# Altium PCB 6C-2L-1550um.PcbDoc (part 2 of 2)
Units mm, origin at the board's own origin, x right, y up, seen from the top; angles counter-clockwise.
Board outline 120.5 x 75.92 mm, 2 copper layers (Top Layer, Bottom Layer), stack 1.586 mm thick; 122 components, 111 nets, 420 pads, 133 vias.
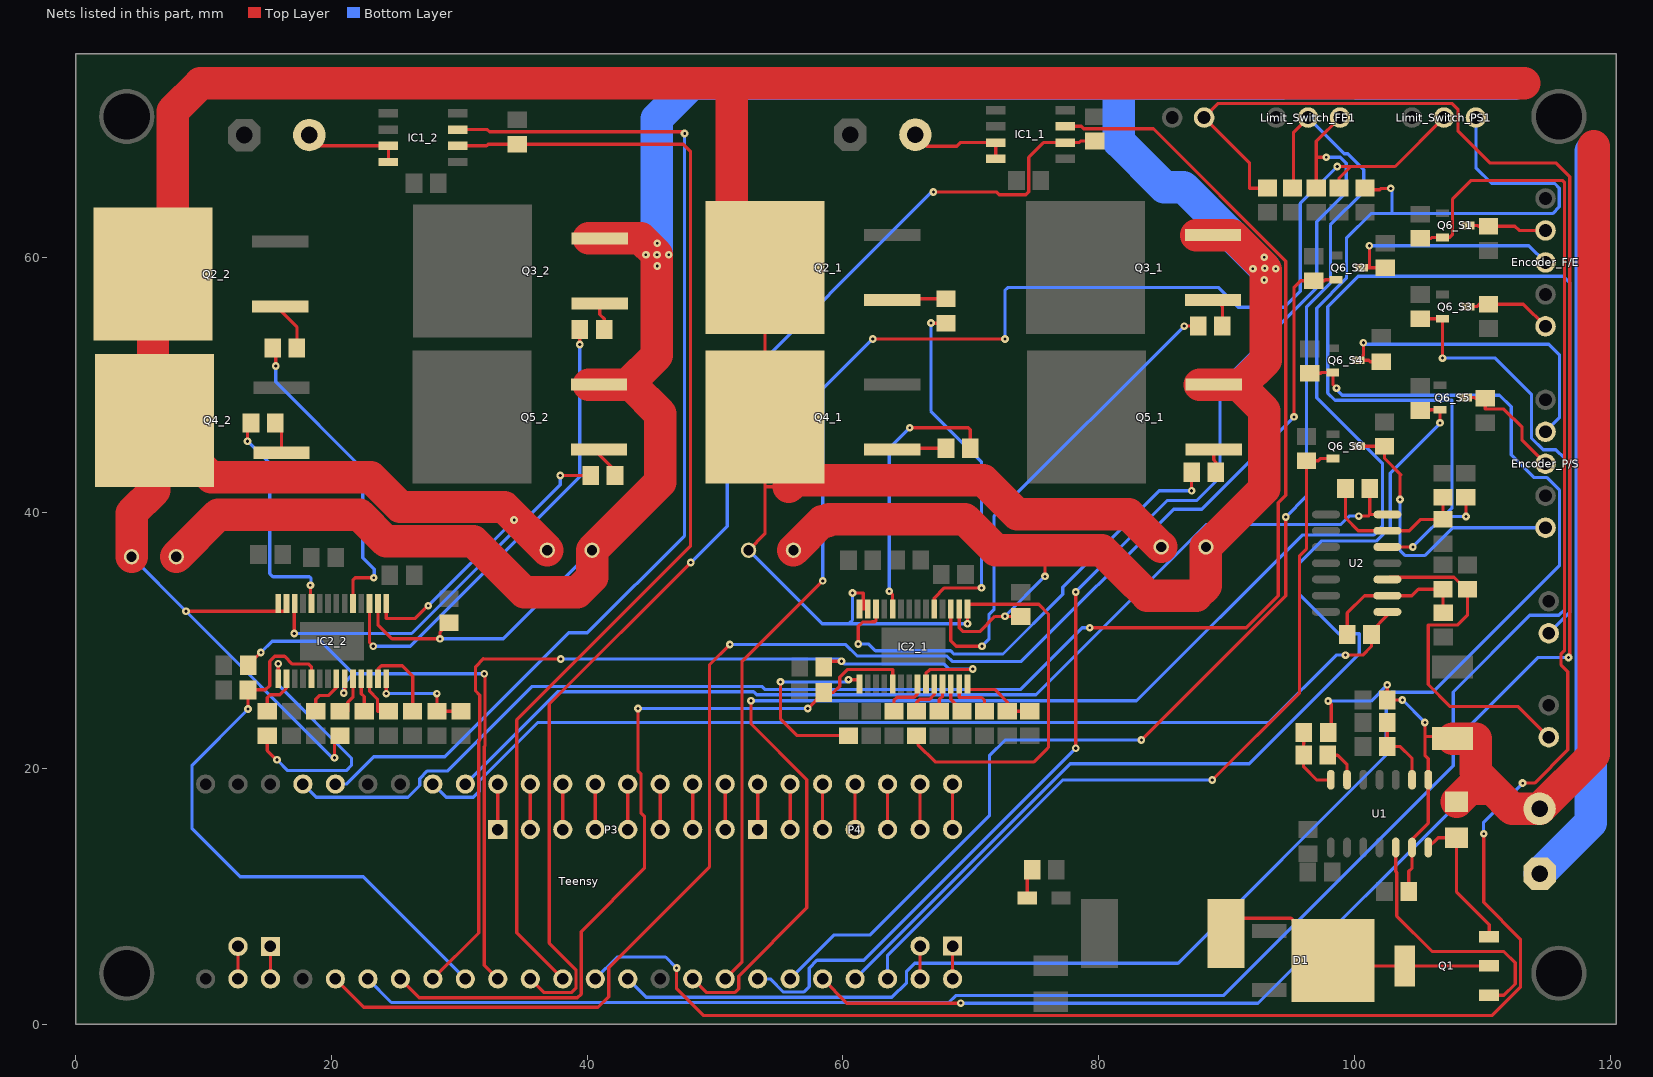
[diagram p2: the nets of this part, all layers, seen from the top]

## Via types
v1: diameter 0.6, hole 0.25, Top Layer to Bottom Layer, 89 vias
v2: diameter 0.6, hole 0.2, Top Layer to Bottom Layer, 44 vias

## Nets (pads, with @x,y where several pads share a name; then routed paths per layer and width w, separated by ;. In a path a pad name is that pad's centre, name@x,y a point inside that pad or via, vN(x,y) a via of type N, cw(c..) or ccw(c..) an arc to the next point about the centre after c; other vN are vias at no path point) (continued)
NetC14_1_2: C14_1.2 IC2_1.15 | length 15.4
  Top Layer w0.254: v1(55.13,26.784) 55.13,23.879 56.426,22.584 C14_1.2@60.452,22.584 ; v1(60.439,26.962) 61.298,26.962 IC2_1.15@61.298,26.611
  Bottom Layer w0.254: v1(55.13,26.784) 60.261,26.784 v1(60.439,26.962)
NetC14_2_1: C14_2.1 IC2_2.16 | length 3.6
  Top Layer w0.254: C14_2.1@14.986,24.486 14.986,25.539 15.228,25.781 15.977,25.781 16.491,26.295 IC2_2.16@16.491,27.034
NetC14_2_2: C14_2.2 IC2_2.15 | length 20.1
  Top Layer w0.254: C14_2.2@14.986,22.586 14.986,21.411 15.697,20.7 v1(15.748,20.7) ; IC2_2.15@15.841,27.034 v1(15.841,28.206)
  Bottom Layer w0.254: v1(15.748,20.7) 16.598,19.85 21.17,19.85 21.577,20.256 21.577,20.816 15.841,26.552 v1(15.841,28.206)
NetD1_3: D1.3 L1.1 Q1.2 Q1.4 | length 23.3
  Top Layer w0.254: L1.1@89.964,7.112 89.964,8.293 95.053,8.293 D1.3@98.346,5 98.774,4.572 Q1.4@103.934,4.572 Q1.2@110.534,4.572
NetD2_2: D2.2 R4.2 | length 2.4
  Top Layer w0.254: D2.2@74.419,9.881 74.419,11.706 R4.2@74.803,12.09
NetEncoder_F/E_2: Encoder_F/E.2 Q6_S1.3 R44_S1.1 | length 6.2
  Top Layer w0.254: Q6_S1.3@108.888,62.484 109.639,62.484 109.705,62.418 R44_S1.1@110.49,62.418 112.56,62.418 112.886,62.092 Encoder_F/E.2@114.956,62.092
NetEncoder_F/E_3: Encoder_F/E.3 Q6_S2.3 R44_S2.1 | length 17.9
  Top Layer w0.254: Q6_S2.3@100.568,59.182 101.18,59.182 ; v1(101.18,60.896) 101.18,59.182 ; R44_S2.1@102.424,59.182 101.18,59.182
  Bottom Layer w0.254: v1(101.18,60.896) 113.652,60.896 Encoder_F/E.3@114.956,59.592
NetEncoder_F/E_5: Encoder_F/E.5 Q6_S3.3 R44_S3.1 | length 6.9
  Top Layer w0.254: Q6_S3.3@108.888,56.134 109.588,56.134 109.776,56.322 R44_S3.1@110.49,56.322 113.226,56.322 Encoder_F/E.5@114.956,54.592
NetEncoder_P/S_2: Encoder_P/S.2 Q6_S4.3 R44_S4.1 | length 25.6
  Top Layer w0.254: v1(100.711,53.315) 100.711,52.335 Q6_S4.3@100.314,51.938 101.13,51.938 101.252,51.816 R44_S4.1@102.108,51.816
  Bottom Layer w0.254: v1(100.711,53.315) 100.826,53.2 115.201,53.2 116.039,52.362 116.039,47.427 Encoder_P/S.2@114.956,46.344
NetEncoder_P/S_3: Encoder_P/S.3 Q6_S5.3 R44_S5.1 | length 9.5
  Top Layer w0.254: Q6_S5.3@108.696,49.022 109.41,49.022 109.476,48.956 R44_S5.1@110.236,48.956 110.236,48.12 111.696,48.12 113.118,46.697 113.118,45.682 Encoder_P/S.3@114.956,43.844
NetEncoder_P/S_5: Encoder_P/S.5 Q6_S6.3 R44_S6.1 | length 23.2
  Top Layer w0.254: Q6_S6.3@100.33,45.212 R44_S6.1@102.362,45.212 102.362,44.259 103.632,42.989 103.581,42.938 v1(103.581,41.046)
  Bottom Layer w0.254: v1(103.581,41.046) 103.581,37.059 103.962,36.678 105.537,36.678 107.703,38.844 Encoder_P/S.5@114.956,38.844
NetIC1_1_3: IC1_1.3 IC1_1.4 P2_1.2 | length 8
  Top Layer w0.254: P2_1.2@65.675,69.579 66.572,68.682 68.909,68.682 69.189,68.961 IC1_1.3@71.964,68.961 IC1_1.4@71.964,67.691
NetIC1_1_6: IC1_1.6 R36_1.2 Teensy.11 | length 95.8
  Top Layer w0.254: Teensy.11@35.56,3.556 36.615,2.501 38.798,2.501 39.129,2.833 39.129,4.278 37.045,6.362 37.045,25.057 v1(48.108,36.119) ; v1(67.081,65.1) 72.009,65.1 72.225,64.884 74.307,64.884 74.536,65.112 74.536,67.805 75.692,68.961 IC1_1.6@77.388,68.961 78.473,68.961 78.6,69.088 R36_1.2@79.705,69.088
  Bottom Layer w0.254: v1(48.108,36.119) 50.952,38.964 50.952,49.098 66.954,65.1 v1(67.081,65.1)
NetIC1_1_7: IC1_1.7 Teensy.28 | length 131.8
  Top Layer w0.254: IC1_1.7@77.388,70.231 78.651,70.231 78.842,70.04 84.297,70.04 94.64,59.697 94.64,41.391 94.061,40.812 94.061,33.523 91.551,31.013 v2(79.299,31.013)
  Bottom Layer w0.254: Teensy.28@17.78,18.796 18.809,17.767 25.996,17.767 26.911,18.681 26.911,19.222 27.514,19.825 29.096,19.825 35.701,26.43 53.673,26.43 53.917,26.186 73.888,26.186 78.715,31.013 v2(79.299,31.013)
NetIC1_2_3: IC1_2.3 IC1_2.4 P2_2.2 | length 8.3
  Top Layer w0.254: P2_2.2@18.279,69.554 18.279,68.707 IC1_2.3@24.466,68.707 IC1_2.4@24.466,67.437
NetIC1_2_6: IC1_2.6 R36_2.2 Teensy.12 | length 90.3
  Top Layer w0.254: IC1_2.6@29.89,68.707 32.143,68.707 32.27,68.834 R36_2.2@34.544,68.834 47.523,68.834 48.082,68.275 48.082,37.389 34.505,23.812 34.505,7.151 Teensy.12@38.1,3.556
NetIC1_2_7: IC1_2.7 Teensy.29 | length 84.7
  Top Layer w0.254: IC1_2.7@29.89,69.977 32.206,69.977 32.379,69.805 47.493,69.805 v2(47.625,69.672)
  Bottom Layer w0.254: Teensy.29@20.32,18.796 21.177,18.796 23.308,20.927 28.877,20.927 38.569,30.619 40.017,30.619 47.625,38.227 v2(47.625,69.672)
NetIC2_1_3: IC2_1.3 R23_1.2 | length 37.8
  Top Layer w0.254: IC2_1.3@68.448,32.487 68.448,30.01 68.88,29.578 v1(70.878,29.578) ; v1(86.702,54.61) R23_1.2@87.784,54.61
  Bottom Layer w0.254: v1(70.878,29.578) 71.425,30.124 71.425,32.052 71.826,32.454 71.826,34.546 71.818,34.554 71.818,39.726 v1(86.702,54.61)
NetIC2_1_5: IC2_1.5 R22_1.2 | length 28.4
  Top Layer w0.254: v1(66.89,54.851) 66.899,54.842 R22_1.2@68.072,54.842 ; IC2_1.5@67.148,32.487 67.148,33.341 67.945,34.138 v1(70.841,34.138)
  Bottom Layer w0.254: v1(66.89,54.851) 66.89,47.967 70.841,44.017 v1(70.841,34.138)
NetIC2_1_10: IC2_1.10 R31_1.2 | length 21.2
  Top Layer w0.254: v2(63.627,33.884) 63.881,33.63 63.881,32.504 IC2_1.10@63.898,32.487 ; v2(65.227,46.66) 69.825,46.66 69.972,46.512 R31_1.2@69.972,45.058
  Bottom Layer w0.254: v2(63.627,33.884) 63.627,45.06 v2(65.227,46.66)
NetIC2_1_12: IC2_1.12 R33_1.2 | length 37.3
  Top Layer w0.254: v1(61.214,29.743) 61.214,31.14 61.543,31.47 62.289,31.47 62.302,31.483 62.488,31.483 62.598,31.593 IC2_1.12@62.598,32.487 ; v1(87.276,41.727) R33_1.2@87.276,43.18
  Bottom Layer w0.254: v1(61.214,29.743) 62.026,29.743 62.552,29.217 68.428,29.217 68.677,28.968 72.529,28.968 77.191,33.63 77.191,34.188 84.73,41.727 v1(87.276,41.727)
NetIC2_1_19: IC2_1.19 R34_1.1 Teensy.7 | length 62.2
  Top Layer w0.254: Teensy.7@25.4,3.556 26.87,2.086 39.248,2.086 39.536,2.374 39.536,7.252 44.488,12.204 44.488,16.269 44.209,16.548 44.209,19.594 43.98,19.824 v1(43.98,24.701) ; v1(57.251,24.701) 58.508,25.959 R34_1.1@58.517,25.959 59.27,25.959 59.753,26.441 59.753,27.165 60.337,27.749 63.898,27.749 IC2_1.19@63.898,26.611
  Bottom Layer w0.254: v1(43.98,24.701) v1(57.251,24.701)
NetIC2_1_22: IC2_1.22 R32_1.1 | length 3.7
  Top Layer w0.254: R32_1.1@63.995,24.484 63.995,25.336 64.253,25.594 65.57,25.594 65.848,25.872 IC2_1.22@65.848,26.611
NetIC2_1_23: IC2_1.23 R28_1.2 Teensy.8 | length 71.8
  Top Layer w0.254: Teensy.8@27.94,3.556 31.534,7.15 31.534,22.161 31.61,22.237 31.61,25.742 31.28,26.073 31.28,27.978 31.889,28.587 31.901,28.575 v1(37.948,28.575) ; R28_1.2@58.52,27.94 58.977,28.397 v1(59.893,28.397) ; IC2_1.23@66.498,26.611 66.498,27.459 66.789,27.749 70.116,27.749 v1(70.167,27.8)
  Bottom Layer w0.254: v1(37.948,28.575) 59.715,28.575 v1(59.893,28.397) 60.096,28.194 67.876,28.194 68.27,27.8 v1(70.167,27.8)
NetIC2_1_24: IC2_1.24 R30_1.1 | length 3.2
  Top Layer w0.254: R30_1.1@65.767,24.484 65.767,25.187 66.017,25.438 66.789,25.438 67.148,25.797 IC2_1.24@67.148,26.611
NetIC2_1_25: IC2_1.25 R29_1.1 | length 2.2
  Top Layer w0.254: R29_1.1@67.539,24.484 67.539,25.412 67.798,25.672 IC2_1.25@67.798,26.611
NetIC2_1_26: IC2_1.26 R27_1.1 | length 2.8
  Top Layer w0.254: IC2_1.26@68.448,26.611 68.448,25.412 68.753,25.107 68.753,24.484 R27_1.1@69.31,24.484
NetIC2_1_27: IC2_1.27 R26_1.1 | length 4
  Top Layer w0.254: IC2_1.27@69.098,26.611 69.098,25.565 70.853,25.565 71.082,25.336 R26_1.1@71.082,24.484
NetIC2_1_28: IC2_1.28 R24_1.2 R25_1.1 | length 6.4
  Top Layer w0.254: IC2_1.28@69.748,26.611 69.748,26.2 71.869,26.2 72.854,25.215 R25_1.1@72.854,24.484 R24_1.2@74.625,24.484
NetIC2_2_3: IC2_2.3 R23_2.2 | length 36.6
  Top Layer w0.254: IC2_2.3@22.991,32.91 22.991,29.857 v1(23.27,29.578) ; v1(39.433,53.174) 39.436,53.177 R23_2.2@39.436,54.356
  Bottom Layer w0.254: v1(23.27,29.578) 26.174,29.578 39.433,42.837 v1(39.433,53.174)
NetIC2_2_5: IC2_2.5 R22_2.2 | length 25
  Top Layer w0.254: R22_2.2@15.408,52.908 15.248,52.748 15.646,52.349 v1(15.646,51.486) ; IC2_2.5@21.691,32.91 21.691,34.747 21.869,34.925 v2(23.317,34.925)
  Bottom Layer w0.254: v1(15.646,51.486) 15.646,50.241 22.454,43.434 22.454,36.5 23.355,35.598 23.355,34.963 v2(23.317,34.925) v2@23.241,34.925
NetIC2_2_10: IC2_2.10 R31_2.2 | length 18.1
  Top Layer w0.254: v1(13.449,45.605) 13.449,46.769 R31_2.2@13.721,47.041 ; v2(18.364,34.341) 18.364,32.987 IC2_2.10@18.441,32.91
  Bottom Layer w0.254: v1(13.449,45.605) 15.176,43.878 15.176,35.255 15.43,35.001 18.288,35.001 18.415,34.874 18.415,34.29 v2(18.364,34.341)
NetIC2_2_12: IC2_2.12 R33_2.2 | length 31.1
  Top Layer w0.254: v1@17.141,30.603 v1(17.106,30.568) 17.106,32.875 IC2_2.12@17.141,32.91 ; v1(37.897,42.926) R33_2.2@40.286,42.926
  Bottom Layer w0.254: v1(17.106,30.568) 26.276,30.568 37.897,42.189 v1(37.897,42.926)
NetIC2_2_19: IC2_2.19 R34_2.1 Teensy.9 | length 47.3
  Top Layer w0.254: v1(13.484,24.66) R34_2.1@13.484,26.162 14.846,26.162 15.176,26.492 15.176,28.384 15.582,28.79 16.344,28.79 16.954,28.181 18.238,28.181 18.441,27.978 IC2_2.19@18.441,27.034
  Bottom Layer w0.254: v1(13.484,24.66) 9.105,20.281 9.105,15.303 12.865,11.544 22.492,11.544 Teensy.9@30.48,3.556
NetIC2_2_22: IC2_2.22 R32_2.1 | length 3.6
  Top Layer w0.254: R32_2.1@18.777,24.486 18.777,25.42 19.087,25.73 19.795,25.73 20.391,26.326 IC2_2.22@20.391,27.034
NetIC2_2_23: IC2_2.23 R28_2.2 Teensy.10 | length 47.6
  Top Layer w0.254: R28_2.2@13.487,28.092 13.5,28.092 v1(14.49,29.083) ; v1(20.967,25.92) 21.041,25.994 IC2_2.23@21.041,27.034 ; v1(31.965,27.419) 32.016,27.368 32.016,21.773 31.965,21.722 31.965,4.611 Teensy.10@33.02,3.556
  Bottom Layer w0.254: v1(14.49,29.083) 15.379,29.972 19.176,29.972 21.729,27.419 ; v1@20.98,25.933 v1(20.967,25.92) 20.967,26.657 21.729,27.419 ; v1(31.965,27.419) 21.729,27.419
NetIC2_2_24: IC2_2.24 R30_2.1 | length 3.3
  Top Layer w0.254: R30_2.1@20.672,24.486 21.282,24.486 21.282,25.184 21.691,25.593 IC2_2.24@21.691,27.034
NetIC2_2_25: IC2_2.25 R29_2.1 | length 2.6
  Top Layer w0.254: IC2_2.25@22.341,27.034 22.341,25.868 22.568,25.641 R29_2.1@22.568,24.486
NetIC2_2_26: IC2_2.26 R27_2.1 | length 3.7
  Top Layer w0.254: IC2_2.26@22.991,27.034 22.991,26.055 23.609,25.438 23.609,24.486 R27_2.1@24.463,24.486
NetIC2_2_27: IC2_2.27 R26_2.1 | length 6.7
  Top Layer w0.254: IC2_2.27@23.641,27.034 23.641,27.781 23.914,28.054 25.539,28.054 26.359,27.234 R26_2.1@26.359,24.486
NetIC2_2_28: IC2_2.28 R24_2.2 R25_2.1 | length 8.4
  Top Layer w0.254: v1(24.291,25.869) IC2_2.28@24.291,27.034 ; v1(28.254,25.869) R25_2.1@28.254,24.486 R24_2.2@30.15,24.486
  Bottom Layer w0.254: v1(24.291,25.869) v1(28.254,25.869)
NetLimit_Switch_FE1_2: Limit_Switch_FE1.2 R6.2 Teensy.19 | length 101.9
  Top Layer w0.254: v1(83.35,22.237) 94.64,33.528 v1(94.64,39.675) ; R6.2@95.25,65.278 95.25,69.783 Limit_Switch_FE1.2@96.384,70.917
  Bottom Layer w0.254: Teensy.19@55.88,3.556 59.321,6.997 62.141,6.997 71.462,16.319 71.462,21.018 72.682,22.237 v1(83.35,22.237) ; v1(94.64,39.675) 96.253,41.287 96.253,56.095 98.132,57.975 98.132,62.522 100.736,65.126 100.736,66.847 99.504,68.079 99.221,68.079 Limit_Switch_FE1.2@96.384,70.917
NetLimit_Switch_FE1_3: Limit_Switch_FE1.3 R10.2 Teensy.18 | length 98.9
  Top Layer w0.254: v1(78.219,21.602) v1(78.219,33.82) ; R10.2@97.028,65.278 R10.2@97.028,65.415 97.028,69.061 Limit_Switch_FE1.3@98.884,70.917 ; 97.028,67.843 97.053,67.818 v2(97.815,67.818)
  Bottom Layer w0.254: Teensy.18@53.34,3.556 54.33,3.556 55.359,2.527 56.933,2.527 57.365,2.959 57.365,4.406 57.975,5.016 61.633,5.016 v1(78.219,21.602) ; v1(78.219,33.82) 85.369,40.97 87.681,40.97 89.496,42.786 89.496,50.05 97.066,57.619 97.066,62.776 99.377,65.087 99.377,67.349 98.908,67.818 v2(97.815,67.818)
NetLimit_Switch_PS1_2: Limit_Switch_PS1.2 R2.2 Teensy.17 | length 116.5
  Top Layer w0.254: Teensy.17@50.8,3.556 52.108,4.864 52.108,28.359 v1(58.432,34.683) ; v1(62.344,53.606) v1(72.682,53.606) ; v1(98.666,67.094) 99.72,67.094 ; R2.2@98.806,65.212 R2.2@98.806,65.415 98.806,66.179 99.72,67.094 ; Limit_Switch_PS1.2@107.012,70.917 103.188,67.094 99.72,67.094
  Bottom Layer w0.254: v1(58.432,34.683) 58.432,49.695 v1(62.344,53.606) ; v1(72.682,53.606) 72.682,57.416 72.885,57.619 89.396,57.619 90.932,56.083 94.539,56.083 95.777,57.322 95.777,64.205 v1(98.666,67.094)
NetLimit_Switch_PS1_3: Limit_Switch_PS1.3 R3.2 Teensy.16 | length 145.6
  Top Layer w0.254: Teensy.16@48.26,3.556 49.315,2.501 51.574,2.501 51.854,2.781 51.854,3.771 57.188,9.105 57.188,19.138 52.819,23.507 v1(52.819,25.311) ; R3.2@100.838,65.278 102.006,65.278 102.108,65.38 v1(102.845,65.38)
  Bottom Layer w0.254: v1(52.819,25.311) 82.969,25.311 95.923,38.265 101.511,38.265 102.196,38.95 102.196,43.878 97.066,49.009 97.066,56.019 99.384,58.338 99.384,61.487 101.307,63.411 115.506,63.411 116.035,63.94 116.035,65.396 115.658,65.773 110.731,65.773 109.512,66.992 Limit_Switch_PS1.3@109.512,70.917 ; v1(102.845,65.38) 102.958,65.266 102.958,63.411
NetP3_1: P3.1 Teensy.34 | length 3.7
  Top Layer w0.254: Teensy.34@33.02,18.796 33.02,15.494 P3.1@33.274,15.24
NetP3_2: P3.2 Teensy.35 | length 3.7
  Top Layer w0.254: Teensy.35@35.56,18.796 35.56,15.494 P3.2@35.814,15.24
NetP3_3: P3.3 Teensy.36 | length 3.7
  Top Layer w0.254: Teensy.36@38.1,18.796 38.1,15.494 P3.3@38.354,15.24
NetP3_4: P3.4 Teensy.37 | length 3.7
  Top Layer w0.254: Teensy.37@40.64,18.796 40.64,15.494 P3.4@40.894,15.24
NetP3_5: P3.5 Teensy.38 | length 3.7
  Top Layer w0.254: Teensy.38@43.18,18.796 43.18,15.494 P3.5@43.434,15.24
NetP3_6: P3.6 Teensy.39 | length 3.7
  Top Layer w0.254: Teensy.39@45.72,18.796 45.72,15.494 P3.6@45.974,15.24
NetP3_7: P3.7 Teensy.40 | length 3.7
  Top Layer w0.254: Teensy.40@48.26,18.796 48.26,15.494 P3.7@48.514,15.24
NetP3_8: P3.8 Teensy.41 | length 3.7
  Top Layer w0.254: Teensy.41@50.8,18.796 50.8,15.494 P3.8@51.054,15.24
NetP4_1: P4.1 Teensy.42 | length 3.7
  Top Layer w0.254: Teensy.42@53.34,18.796 53.34,15.494 P4.1@53.594,15.24
NetP4_2: P4.2 Teensy.43 | length 3.7
  Top Layer w0.254: Teensy.43@55.88,18.796 55.88,15.494 P4.2@56.134,15.24
NetP4_3: P4.3 Teensy.44 | length 3.7
  Top Layer w0.254: Teensy.44@58.42,18.796 58.42,15.494 P4.3@58.674,15.24
NetP4_4: P4.4 Teensy.45 | length 3.7
  Top Layer w0.254: Teensy.45@60.96,18.796 60.96,15.494 P4.4@61.214,15.24
NetP4_5: P4.5 Teensy.46 | length 3.7
  Top Layer w0.254: Teensy.46@63.5,18.796 63.5,15.494 P4.5@63.754,15.24
NetP4_6: P4.6 Teensy.47 | length 3.7
  Top Layer w0.254: Teensy.47@66.04,18.796 66.04,15.494 P4.6@66.294,15.24
NetP4_7: P4.7 Teensy.48 | length 3.7
  Top Layer w0.254: Teensy.48@68.58,18.796 68.58,15.494 P4.7@68.834,15.24
NetP5_1: P5.1 Teensy.3 | length 2.5
  Top Layer w0.254: Teensy.3@15.24,3.556 P5.1@15.24,6.096
NetP5_2: P5.2 Teensy.2 | length 2.5
  Top Layer w0.254: Teensy.2@12.7,3.556 P5.2@12.7,6.096
NetP6_1: P6.1 Teensy.24 | length 2.5
  Top Layer w0.254: Teensy.24@68.58,3.556 68.58,5.837 68.585,5.842 P6.1@68.834,5.842
NetP6_2: P6.2 Teensy.23 | length 2.4
  Top Layer w0.254: Teensy.23@66.04,3.556 66.04,5.588 P6.2@66.294,5.842
NetPt1_2: Pt1.2 R15.1 U2.3 | length 28
  Top Layer w0.254: U2.3@102.59,34.798 102.757,34.965 107.8,34.965 108.739,34.026 R15.1@108.864,34.026 ; R15.1@108.859,34.102 108.859,32.042 108.046,31.229 105.778,31.229 105.778,26.581 107.505,24.853 112.817,24.853 Pt1.2@115.21,22.46
NetPt2_2: Pt2.2 R19.1 U2.5 | length 83.8
  Top Layer w0.254: U2.5@102.59,37.338 v1(104.584,37.338) ; R19.1@108.712,41.148 108.737,41.123 v1(108.737,39.726)
  Bottom Layer w0.254: v1(104.584,37.338) 107.645,40.399 ; v1(108.737,39.726) 106.972,39.726 107.645,40.399 ; Pt2.2@115.21,30.588 116.852,32.23 116.852,58 116.344,58.508 100.317,58.508 97.929,56.121 97.929,49.369 98.492,48.806 107.645,48.806 107.645,40.399
NetQ1_1: Q1.1 U1.12 | length 20.3
  Top Layer w0.254: U1.12@103.246,13.836 103.246,11.95 103.314,11.882 103.314,8.47 106.083,5.702 111.696,5.702 112.585,4.813 112.585,3.161 111.696,2.272 Q1.1@110.534,2.272
NetQ1_3: Q1.3 R1.2 U1.14 | length 11.3
  Top Layer w0.254: U1.14@105.786,13.836 106.55,14.6 R1.2@108,14.6 108,10.35 110.553,7.797 110.553,6.872 Q1.3@110.534,6.872
NetQ2_1_1: Q2_1.1 R22_1.1 | length 4.3
  Top Layer w0.254: Q2_1.1@63.858,56.642 65.9,56.642 66,56.742 R22_1.1@68.072,56.742
NetQ2_2_1: Q2_2.1 R22_2.1 | length 3.8
  Top Layer w0.254: Q2_2.1@16.002,56.134 16.002,55.855 17.308,54.549 R22_2.1@17.308,52.908
NetQ3_1_1: Q3_1.1 R23_1.1 | length 2.5
  Top Layer w0.254: Q3_1.1@88.944,56.642 89.205,56.642 89.684,56.163 R23_1.1@89.684,54.61
NetQ3_2_1: Q3_2.1 R23_2.1 | length 2.2
  Top Layer w0.254: Q3_2.1@40.998,56.388 40.998,55.519 41.336,55.181 R23_2.1@41.336,54.356
NetQ4_1_1: Q4_1.1 R31_1.1 | length 4.3
  Top Layer w0.254: Q4_1.1@63.858,44.958 65.9,44.958 66,45.058 R31_1.1@68.072,45.058
NetQ4_2_1: Q4_2.1 R31_2.1 | length 2.5
  Top Layer w0.254: R31_2.1@15.621,47.041 16.106,46.556 Q4_2.1@16.106,44.704
NetQ5_1_1: Q5_1.1 R33_1.1 | length 1.8
  Top Layer w0.254: Q5_1.1@89.004,44.958 89.004,44.152 89.176,43.98 R33_1.1@89.176,43.18
NetQ5_2_1: Q5_2.1 R33_2.1 | length 2.5
  Top Layer w0.254: Q5_2.1@40.938,44.958 40.938,44.542 42.186,43.294 R33_2.1@42.186,42.926
NetQ6_S1_2: Q6_S1.2 R43_S1.1 Teensy.13 | length 159.4
  Top Layer w0.254: v1(47.002,4.406) 47.002,2.781 49.085,0.698 110.782,0.698 112.991,2.908 112.991,6.667 110.121,9.537 v2(110.121,14.897) ; R43_S1.1@105.156,61.468 105.981,61.468 106.047,61.534 Q6_S1.2@106.888,61.534 107.429,61.534 107.683,61.788 107.683,64.554 109.131,66.001 116.268,66.001 116.446,65.824 116.446,29.258 116.171,28.983 116.171,28.099 116.7,27.57 116.7,21.475 114.097,18.872 v2(113.157,18.872)
  Bottom Layer w0.254: Teensy.13@40.64,3.556 42.354,5.27 46.139,5.27 v1(47.002,4.406) ; v2(110.121,14.897) 110.109,14.909 110.109,15.824 v2(113.157,18.872)
NetQ6_S2_2: Q6_S2.2 R43_S2.1 Teensy.5 | length 120.3
  Top Layer w0.254: Teensy.5@20.32,3.556 22.543,1.333 40.855,1.333 41.694,2.171 41.694,4.432 49.568,12.306 49.568,28.105 v1(51.168,29.705) ; v1(95.288,47.51) 95.288,57.645 95.809,58.166 R43_S2.1@96.836,58.166 97.65,58.166 97.716,58.232 Q6_S2.2@98.568,58.232
  Bottom Layer w0.254: v1(51.168,29.705) 60.239,29.705 61.133,28.811 68.123,28.811 68.55,28.384 73.952,28.384 85.864,40.297 88.074,40.297 v1(95.288,47.51)
NetQ6_S3_2: Q6_S3.2 R43_S3.1 Teensy.6 | length 141.9
  Top Layer w0.254: R43_S3.1@105.156,55.184 Q6_S3.2@106.888,55.184 106.895,55.184 v1(106.895,52.108)
  Bottom Layer w0.254: Teensy.6@22.86,3.556 24.702,1.714 68.283,1.714 68.823,2.253 89.756,2.253 107.734,20.231 107.734,25.996 113.728,31.991 115.989,31.991 116.446,32.448 116.446,44.259 115.76,44.945 114.769,44.945 113.855,45.859 113.855,49.288 111.036,52.108 v1(106.895,52.108)
NetQ6_S4_2: Q6_S4.2 R43_S4.1 Teensy.14 | length 122.7
  Top Layer w0.254: R43_S4.1@96.52,50.922 97.37,50.922 97.436,50.988 Q6_S4.2@98.314,50.988 98.336,50.988 98.336,50.025 v1(98.603,49.758)
  Bottom Layer w0.254: Teensy.14@43.18,3.556 44.616,2.12 63.842,2.12 64.985,3.263 64.985,4.152 65.62,4.787 86.22,4.787 102.501,21.069 102.501,25.539 102.933,25.971 106.133,25.971 116.039,35.877 116.039,41.795 115.074,42.76 114.058,42.76 112.27,44.549 112.27,48.298 111.355,49.212 99.047,49.212 98.603,49.656 v1(98.603,49.758)
NetQ6_S5_2: Q6_S5.2 R43_S5.1 Teensy.21 | length 80.6
  Top Layer w0.254: R43_S5.1@105.156,48.006 105.879,48.006 105.945,48.072 Q6_S5.2@106.696,48.072 106.705,48.063 v1(106.705,47.041)
  Bottom Layer w0.254: Teensy.21@60.96,3.556 77.793,20.389 91.788,20.389 100.396,28.997 100.396,30.556 98.781,30.556 95.719,33.617 95.719,36.106 97.409,37.795 101.702,37.795 102.806,38.9 102.806,43.11 v1@106.721,47.025
NetQ6_S6_2: Q6_S6.2 R43_S6.1 Teensy.22 | length 63.1
  Top Layer w0.254: v1(88.887,19.113) 95.719,25.946 95.719,36.664 96.266,37.211 R43_S6.1@96.266,44.074 97.193,44.074 97.381,44.262 Q6_S6.2@98.33,44.262
  Bottom Layer w0.254: Teensy.22@63.5,3.556 63.5,5.41 77.203,19.113 v1(88.887,19.113)
NetR5_1: R5.1 R9.2 U1.2 | length 5.8
  Top Layer w0.254: R9.2@102.584,23.598 R5.1@102.584,21.742 103.568,21.742 104.516,20.794 U1.2@104.516,19.136
NetR7_2: R7.2 R8.1 U1.7 | length 5.3
  Top Layer w0.254: R7.2@96.053,22.835 96.053,21.951 96.034,21.932 R8.1@96.034,21.058 96.034,20.145 97.066,19.113 98.166,19.113 U1.7@98.166,19.136
NetR8_2: R8.2 U1.6 | length 3
  Top Layer w0.254: R8.2@97.934,21.058 98.691,21.058 99.436,20.313 U1.6@99.436,19.136
NetR12_2: R12.2 Soft_Stop1.2 Teensy.20 | length 151.8
  Top Layer w0.254: Teensy.20@58.42,3.556 60.313,1.663 v1(69.227,1.663) ; R12.2@93.218,65.4 91.796,65.4 91.796,67.377 Soft_Stop1.2@88.256,70.917 89.36,72.021 107.632,72.021 108.115,71.539 108.115,69.837 110.578,67.373 115.76,67.373 116.852,66.281 116.852,28.79 v1(116.751,28.689)
  Bottom Layer w0.254: v1(69.227,1.663) 92.468,1.663 109.131,18.326 109.131,23.482 114.338,28.689 v1(116.751,28.689)
NetR14_1: R14.1 R16.1 R17.2 U2.2 | length 11.8
  Top Layer w0.254: R14.1@99.446,30.48 99.446,32.177 100.797,33.528 U2.2@102.59,33.528 104.508,33.528 105.016,34.036 R16.1@106.934,34.036 106.934,32.299 R17.2@106.827,32.192
NetR14_2: R14.2 Teensy.32 U2.1 | length 82.4
  Top Layer w0.254: v1(99.314,28.88) 100.66,28.88 101.346,29.566 R14.2@101.346,30.48 101.346,30.746 102.59,31.99 U2.1@102.59,32.258
  Bottom Layer w0.254: Teensy.32@27.94,18.796 28.969,17.767 31.102,17.767 31.559,18.224 31.559,19.037 36.131,23.609 93.31,23.609 98.581,28.88 v1(99.314,28.88)
NetR18_1: R18.1 R20.1 R21.2 U2.6 | length 12.4
  Top Layer w0.254: R18.1@99.314,41.91 99.314,39.611 100.317,38.608 U2.6@102.59,38.608 104.305,38.608 105.189,39.492 R21.2@106.934,39.492 R20.1@106.934,41.214
NetR18_2: R18.2 Teensy.33 U2.7 | length 83.1
  Top Layer w0.254: v1(100.355,39.751) 101.087,39.751 101.214,39.878 ; R18.2@101.214,41.91 101.214,39.878 ; U2.7@102.59,39.878 101.214,39.878
  Bottom Layer w0.254: Teensy.33@30.48,18.796 37.708,26.024 53.022,26.024 53.266,25.78 75.107,25.78 88.422,39.095 98.951,39.095 99.607,39.751 v1(100.355,39.751)
PGND: C6_1.2 C6_2.2 C7_1.2 C7_2.2 IC2_1.2 IC2_2.2 P1.1 Q3_1.3 Q3_2.3 Q5_1.3 Q5_2.3 R35_1.1 R35_2.1 | length 348
  Top Layer w0.254: IC2_2.2@23.641,32.91 23.641,31.247 24.739,30.15 v1(28.498,30.15) 28.498,30.684 R35_2.1@29.21,31.396 ; IC2_1.2@69.098,32.487 69.098,31.026 69.403,30.721 70.716,30.721 71.899,31.904 v1@72.692,31.904 ; v1(72.682,31.915) v1@72.692,31.904 ; R35_1.1@73.914,31.904 v1@72.692,31.904 ; 75.717,37.084 75.806,36.996 v1(75.806,35.039) ; 82.054,35.039 82.182,35.166 ; Q5_1.3@87.909,50.038 88.457,49.491 ; 92.964,44.983 92.976,44.971 92.976,41.262
  Top Layer w2.54: C7_2.2@7.874,36.576 11.151,39.853 22.202,39.853 24.285,37.77 31.115,37.77 35.103,33.782 39.218,33.782 40.39,34.954 C6_2.2@40.39,37.084 45.72,42.414 45.72,47.752 43.434,50.038 43.18,50.038 ; Q5_2.3@40.132,50.038 Q5_2.3@40.938,50.038 43.18,50.038 ; Q3_2.3@40.132,61.468 Q3_2.3@40.998,61.468 44.196,61.468 v2(45.466,60.198) 45.466,52.324 43.18,50.038 ; C7_1.2@56.134,37.084 58.406,39.356 58.773,39.356 58.94,39.522 69.534,39.522 71.972,37.084 75.717,37.084 80.264,37.084 82.182,35.166 83.82,33.528 87.63,33.528 88.396,34.294 C6_1.2@88.396,37.338 92.964,41.906 92.964,44.983 92.964,48.006 Q5_1.3@90.932,50.038 ; Q3_1.3@87.655,61.722 Q3_1.3@88.944,61.722 90.424,61.722 93.002,59.144 v2(92.989,59.131) 93.091,59.03 93.091,51.943 91.186,50.038 Q5_1.3@90.932,50.038 ; Q5_1.3@87.909,50.038 Q5_1.3@89.004,50.038 Q5_1.3@90.932,50.038
  Bottom Layer w0.254: v1(28.498,30.15) 33.456,30.15 C6_2.2@40.39,37.084 ; v1(72.682,31.915) v1(75.806,35.039)
  Bottom Layer w2.54: v2(45.466,60.198) 45.466,70.841 48.178,73.553 81.585,73.553 ; v2(92.989,59.131) 86.639,65.481 85.141,65.481 81.585,69.037 81.585,73.553 ; 112.567,73.553 100.241,73.553 100.21,73.584 94.359,73.584 94.328,73.553 81.585,73.553 ; P1.1@114.49,11.783 118.491,15.783 118.491,68.301
  other v2: 92.964,58.217 92.075,59.106 93.853,59.106 45.491,59.309 92.964,59.995 44.602,60.198 46.38,60.198 45.491,61.087
V+_1: C1.1 C3.2 C5.2 C6_1.1 C6_2.1 C7_1.1 C7_2.1 IC2_1.1 IC2_1.13 IC2_1.14 IC2_2.1 IC2_2.13 IC2_2.14 P1.2 Q2_1.2 Q2_2.2 Q4_1.2 Q4_2.2 R1.1 R7.1 R30_1.2 R30_2.2 U1.1 U1.13 | length 448.4
  Top Layer w0.254: v1(8.634,32.316) 16.491,32.316 IC2_2.13@16.491,32.91 ; v1(20.244,20.853) 20.244,22.157 R30_2.2@20.672,22.586 ; IC2_2.1@24.291,32.91 24.291,31.737 26.53,31.737 27.534,32.741 v2(27.584,32.741) ; C7_1.1@52.634,37.084 53.908,38.358 53.908,42.048 ; Q2_1.2@53.908,59.182 Q4_1.2@53.908,47.498 53.908,42.048 ; 55.789,42.048 53.908,42.048 ; v1(60.757,33.731) 61.595,33.731 61.595,32.487 ; IC2_1.14@61.298,32.487 61.595,32.487 ; IC2_1.13@61.948,32.487 61.595,32.487 ; R30_1.2@65.767,22.584 65.874,22.584 65.874,21.882 67.233,20.523 74.955,20.523 75.912,21.48 75.912,21.487 76.085,21.66 76.085,32.092 75.323,32.854 69.748,32.854 IC2_1.1@69.748,32.487 v1(69.748,31.33) ; R7.1@97.953,22.835 97.953,23.461 98.204,23.461 98.204,25.034 v1(97.953,25.285) ; v1(102.584,26.553) C5.2@102.584,25.376 v1(103.761,25.376) ; C3.2@104.262,10.39 104.262,11.976 104.516,12.23 U1.13@104.516,13.836 104.516,14.473 105.786,15.743 U1.1@105.786,19.136 105.786,20.782 105.524,21.044 105.524,22.518 105.522,22.519 ; v1(105.522,23.615) 105.522,22.519 ; C1.1@107.696,22.352 107.529,22.519 105.522,22.519
  Top Layer w2.54: C7_2.1@4.374,36.576 4.374,39.985 6.156,41.767 Q4_2.2@6.156,47.244 ; C6_2.1@36.89,37.084 33.512,40.462 25.4,40.462 23.063,42.799 10.601,42.799 Q4_2.2@6.156,47.244 ; Q2_1.2@53.908,59.182 51.309,61.781 51.309,73.584 ; 55.789,42.048 56.286,42.545 70.993,42.545 73.66,39.878 82.356,39.878 C6_1.1@84.896,37.338 ; C1.1@107.696,22.352 109.499,22.352 109.499,19.71 110.795,18.415 ; R1.1@108,17.4 109.015,18.415 110.795,18.415 ; 113.284,73.584 51.309,73.584 ; 118.745,68.68 118.745,21.117 P1.2@114.49,16.863 112.347,16.863 110.795,18.415 ; Q4_2.2@6.156,47.244 6.052,47.348 Q2_2.2@6.052,58.674 7.581,60.203 7.581,71.412 9.754,73.584 51.309,73.584
  Bottom Layer w0.254: C7_2.1@4.374,36.576 v1(8.634,32.316) 20.244,20.706 v1(20.244,20.853) ; v2(27.584,32.741) v2(34.29,39.446) ; C7_1.1@52.634,37.084 58.388,31.33 60.693,31.33 ; v1(60.757,33.731) 60.757,31.622 60.579,31.444 60.693,31.33 ; v1(69.748,31.33) 60.693,31.33 ; v1(97.953,25.285) 101.316,25.285 v1(102.584,26.553) ; v1@103.771,25.376 v1@105.524,23.623
pads on no net: Teensy.4 Teensy.15 Teensy.30 Teensy.31 U1.5 U1.9 U1.10 U2.8 U2.9 U2.10 U2.12 U2.13 U2.14

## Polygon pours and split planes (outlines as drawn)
GND on Top Layer "Top Layer-GND" (solid, remove dead copper, pour order 32): 0.254,75.692 0.254,0.254 120.142,0.254 120.142,75.692
NetIC1_2_3 on Top Layer "Top Layer-No Net 1" (solid, pour order 22): 25.228,69.088 25.228,66.294 18.034,66.294 16.256,68.072 16.256,71.882 20.32,71.882 20.32,69.088
V+_1 on Top Layer "Top Layer-No Net" (solid, pour order 2): 49.276,64.516 59.182,64.516 59.182,42.926 54.102,37.846 54.102,35.56 49.276,35.56
NetIC1_1_3 on Top Layer "Top Layer-No Net 1" (solid, pour order 24): 72.726,69.342 72.726,67.146 64.934,67.146 63.754,68.326 63.754,71.857 67.818,71.857 67.818,69.342
V+_1 on Top Layer "Top Layer-No Net" (solid, pour order 0): 1.168,64.16 10.82,64.16 10.82,42.57 5.74,37.49 5.74,35.204 1.168,35.204
NetC13_2_2 on Top Layer "Top Layer-No Net" (solid, pour order 10): 26.113,52.948 23.965,50.8 13.716,50.8 13.716,48.26 24.384,48.26 26.113,46.531 26.113,42.351 26.416,42.048 35.814,42.048 35.814,52.694 35.56,52.948
NetC10_2_2 on Top Layer "Top Layer-No Net" (solid, pour order 8): 13.208,59.69 21.59,59.69 26.173,55.107 26.173,53.478 35.814,53.478 35.814,64.262 18.796,64.262 15.24,67.818 15.24,71.679 10.668,71.679 10.668,67.31 13.324,64.654 13.324,64.378 13.208,64.262
NetC10_1_2 on Top Layer "Top Layer-No Net" (solid, pour order 14): 60.902,59.944 69.284,59.944 73.867,55.361 73.867,53.732 83.508,53.732 83.508,64.516 66.49,64.516 62.934,68.072 62.934,71.577 58.362,71.577 58.362,67.564 61.018,64.908 61.018,64.632 60.902,64.516
NetC13_1_2 on Top Layer "Top Layer-No Net" (solid, pour order 18): 74.119,52.948 72.149,50.978 61.722,50.978 61.722,48.006 72.644,48.006 74.119,46.531 74.119,42.351 74.422,42.048 83.82,42.048 83.82,52.694 83.566,52.948
V+_1 on Top Layer "Top Layer-No Net 1" (solid, pour order 28): 119.892,74.803 113.157,74.803 112.497,74.143 112.497,68.174 119.558,68.174 119.942,68.558
GND on Bottom Layer "Bottom Layer-GND" (solid, remove dead copper, pour order 34): 0.254,75.692 0.254,0.254 120.142,0.254 120.142,75.692
PGND on Bottom Layer "Top Layer-No Net 1" (solid, pour order 30): 119.659,74.6 112.954,74.6 112.497,74.143 112.497,68.174 119.558,68.174 119.71,68.326

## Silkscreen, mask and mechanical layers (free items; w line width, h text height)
Top Overlay:
  lines w0.254: 13.691,20.853 14.072,21.234 ; 14.072,21.184 14.072,21.234 ; 14.478,20.828 14.072,21.234 ; 14.58,17.475 14.503,17.475 14.072,17.907 14.072,21.26 ; 59.03,20.828 59.538,21.336 ; 59.538,11.379 59.538,21.336 ; 60.071,20.803 59.538,21.336 ; 14.072,21.234 14.072,21.26 ; 14.072,21.234 14.072,21.26
  text "Motor_P/S" at 19.533,75.463 h0.76 r180
  text "Motor_F/E" at 66.091,75.413 h0.76 r180
  text "TraDiHab 2019 / Nagiller / Panny" at 1.016,30.48 h1.52 r270
  text "12V" at 120.294,16.561 h0.76 r90
  text "GND" at 120.244,9.957 h0.76 r90
Mechanical 1:
  lines w0.2: 0,75.921 0,0 120.498,0 120.498,75.921 0.025,75.946
  text ".Pcb_File_Name_No_Path" at 0,-2.5 h1.52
